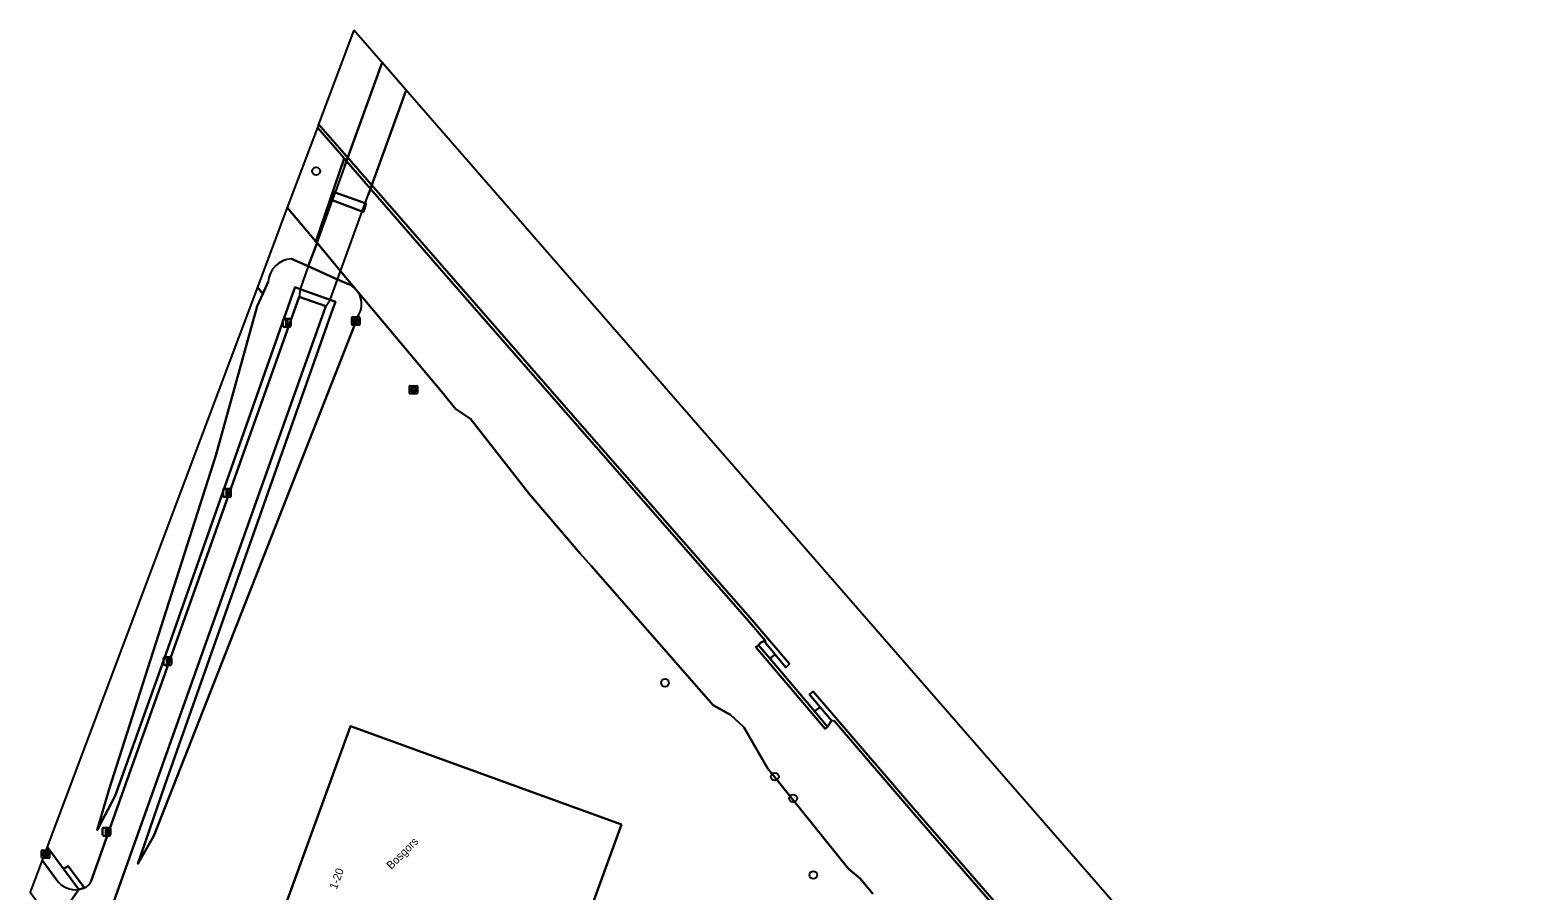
# Model space of a CAD drawing. Extents: x 156661 to 157576, y 383570 to 384425.
# Drawn here: x 156828.2 to 157016.4, y 384317.7 to 384425.3 of the extents above; entities that cross this region are included whole.
import ezdxf

# ---------------------------------------------------------------- set-up
doc = ezdxf.new("R2010")
doc.units = 0
for name, color, linetype in [('IMGEO_Boom', 7, 'Continuous'), ('IMGEO_Dek', 7, 'Continuous'), ('IMGEO_Fietspad_gesloten', 7, 'Continuous'), ('IMGEO_Fietspad_open', 7, 'Continuous'), ('IMGEO_Gemengd_bos', 7, 'Continuous'), ('IMGEO_Groenvoorziening', 7, 'Continuous'), ('IMGEO_Haag', 7, 'Continuous'), ('IMGEO_Hek', 7, 'Continuous'), ('IMGEO_Houtwal', 7, 'Continuous'), ('IMGEO_Kademuur', 7, 'Continuous'), ('IMGEO_Kast', 7, 'Continuous'), ('IMGEO_Lichtmast', 7, 'Continuous'), ('IMGEO_Loofbos', 7, 'Continuous'), ('IMGEO_Oever', 7, 'Continuous'), ('IMGEO_Openbare_ruimte_label', 7, 'Continuous'), ('IMGEO_Pand', 7, 'Continuous'), ('IMGEO_Pand_nummerreeks', 7, 'Continuous'), ('IMGEO_Pijler', 7, 'Continuous'), ('IMGEO_Rioolput', 7, 'Continuous'), ('IMGEO_Voetpad_open', 7, 'Continuous'), ('IMGEO_Waterloop', 7, 'Continuous')]:
    doc.layers.add(name, color=color, linetype=linetype)

msp = doc.modelspace()

# ---------------------------------------------------------------- linework, layer by layer
at = {"layer": 'IMGEO_Boom'}
for centre in [(156863.91, 384407.68), (156907.51, 384343.72), (156921.23, 384331.99), (156923.52, 384329.29), (156926.04, 384319.71)]:
    msp.add_circle(centre, 0.489, dxfattribs=at)
at = {"layer": 'IMGEO_Dek'}
msp.add_lwpolyline([(156875.15, 384417.82), (156872.14, 384421.27), (156867.44, 384408.27), (156866.27, 384405.03), (156865.9, 384404.04), (156863.99, 384398.74), (156862.92, 384395.79), (156861.89, 384392.95), (156861.79, 384391.99), (156865.12, 384390.79), (156865.67, 384391.6), (156866.59, 384394.15), (156866.96, 384395.19), (156869.67, 384402.65), (156870.04, 384403.68), (156870.44, 384404.8)], close=True, dxfattribs=at)
at = {"layer": 'IMGEO_Fietspad_gesloten'}
msp.add_lwpolyline([(156875.15, 384417.82), (156872.14, 384421.27), (156867.44, 384408.27), (156866.27, 384405.03), (156865.9, 384404.04), (156863.99, 384398.74), (156862.92, 384395.79), (156861.89, 384392.95), (156861.79, 384391.99), (156865.12, 384390.79), (156865.67, 384391.6), (156866.59, 384394.15), (156866.96, 384395.19), (156869.67, 384402.65), (156870.04, 384403.68), (156870.44, 384404.8)], close=True, dxfattribs=at)
for points in [[(156829.64, 384321.55), (156828.15, 384317.58), (156831.14, 384313.53), (156834.24, 384317.91)], [(156831.5, 384319.07), (156829.64, 384321.55)]]:
    msp.add_lwpolyline(points, dxfattribs=at)
msp.add_arc((156833.76, 384320.58), 2.71, 213.7247, 280.328, dxfattribs=at)
at = {"layer": 'IMGEO_Fietspad_open'}
for points in [[(156833.16, 384301.08), (156837.53, 384313.35), (156865.12, 384390.79), (156861.79, 384391.99), (156835.74, 384318.86)], [(156834.95, 384318.09), (156834.24, 384317.91), (156831.14, 384313.53)]]:
    msp.add_lwpolyline(points, dxfattribs=at)
msp.add_arc((156834.41, 384319.43), 1.44, 291.7855, 336.9714, dxfattribs=at)
at = {"layer": 'IMGEO_Gemengd_bos'}
for points in [[(156860.3, 384403.15), (156856.56, 384393.19), (156857.24, 384392.35), (156857.91, 384393.84)], [(156860.82, 384396.74), (156862.92, 384395.79), (156864.01, 384398.72), (156863.99, 384398.74), (156863.88, 384398.87), (156860.3, 384403.15)]]:
    msp.add_lwpolyline(points, dxfattribs=at)
msp.add_arc((156861.02, 384393.62), 3.12, 93.7377, 175.9662, dxfattribs=at)
at = {"layer": 'IMGEO_Groenvoorziening'}
for points in [[(156933.49, 384317.37), (156931.89, 384319.27), (156930.43, 384320.47), (156920.32, 384333.08), (156917.35, 384338.18), (156915.68, 384339.71), (156913.54, 384340.93), (156898.26, 384358.33), (156896.92, 384359.9), (156890.54, 384367.33), (156883.2, 384376.71), (156881.32, 384377.98), (156879.76, 384379.88), (156866.96, 384395.19), (156864.01, 384398.72), (156862.92, 384395.79), (156862.92, 384395.79), (156866.59, 384394.15), (156867.93, 384393.54)], [(156867.93, 384393.54), (156866.59, 384394.15), (156862.92, 384395.79), (156862.92, 384395.79), (156860.82, 384396.74)], [(156857.91, 384393.84), (156857.24, 384392.35), (156856.55, 384390.8), (156851.36, 384372.13), (156837.99, 384330.3), (156836.54, 384325.29), (156838.78, 384329.6), (156844.84, 384346.47), (156860.94, 384392.3), (156861.26, 384393.17), (156861.89, 384392.95), (156865.67, 384391.6), (156866.32, 384391.36), (156866, 384390.47), (156844.98, 384330.95), (156841.61, 384321.1), (156843.61, 384324.6), (156869.19, 384389.66)], [(156856.56, 384393.19), (156830.27, 384323.22), (156832.33, 384320.46), (156832.89, 384320.83), (156834.95, 384318.09)], [(156835.74, 384318.86), (156861.79, 384391.99), (156865.12, 384390.79), (156837.53, 384313.35)], [(156869.19, 384389.66), (156843.61, 384324.6), (156841.61, 384321.1), (156844.98, 384330.95), (156866, 384390.47), (156866.32, 384391.36), (156865.67, 384391.6), (156861.89, 384392.95), (156861.26, 384393.17), (156860.94, 384392.3), (156844.84, 384346.47), (156838.78, 384329.6), (156836.54, 384325.29), (156837.99, 384330.3), (156851.36, 384372.13), (156856.55, 384390.8), (156857.24, 384392.35), (156856.56, 384393.19)]]:
    msp.add_lwpolyline(points, dxfattribs=at)
for points in [[(156902.06, 384326.02), (156889.74, 384292.16), (156855.89, 384304.48), (156868.2, 384338.32)], [(156832.89, 384320.83), (156832.33, 384320.46), (156834.24, 384317.91), (156834.95, 384318.09)]]:
    msp.add_lwpolyline(points, close=True, dxfattribs=at)
for centre, radius, start, end in [((156861.02, 384393.62), 3.12, 93.7377, 175.9662), ((156866.88, 384391.06), 2.7, 328.804, 67.0801), ((156866.88, 384391.06), 2.7, 328.804, 67.0801), ((156834.41, 384319.43), 1.44, 291.7855, 336.9714)]:
    msp.add_arc(centre, radius, start, end, dxfattribs=at)
at = {"layer": 'IMGEO_Haag'}
msp.add_lwpolyline([(156832.89, 384320.83), (156832.33, 384320.46), (156834.24, 384317.91), (156834.95, 384318.09)], close=True, dxfattribs=at)
at = {"layer": 'IMGEO_Hek'}
for points in [[(156867.44, 384408.27), (156872.14, 384421.27)], [(156875.15, 384417.82), (156870.44, 384404.8)], [(156867.44, 384408.27), (156866.27, 384405.03)], [(156866.27, 384405.03), (156865.9, 384404.04)], [(156865.9, 384404.04), (156863.99, 384398.74)], [(156869.67, 384402.65), (156870.04, 384403.68)], [(156870.04, 384403.68), (156870.44, 384404.8)], [(156866.96, 384395.19), (156869.67, 384402.65)], [(156863.99, 384398.74), (156862.92, 384395.79)], [(156862.92, 384395.79), (156861.89, 384392.95)], [(156865.67, 384391.6), (156866.59, 384394.15)], [(156866.59, 384394.15), (156866.96, 384395.19)], [(156861.89, 384392.95), (156861.79, 384391.99)], [(156865.12, 384390.79), (156865.67, 384391.6)]]:
    msp.add_lwpolyline(points, dxfattribs=at)
at = {"layer": 'IMGEO_Houtwal'}
msp.add_lwpolyline([(156962.3, 384300.1), (156938.72, 384327.24), (156928.69, 384338.92), (156928.32, 384339.01), (156928.08, 384338.61), (156927.83, 384338.23), (156927.53, 384337.97), (156918.87, 384348.18), (156919.18, 384348.44), (156919.46, 384348.73), (156920.02, 384349.03), (156917.83, 384351.59), (156898.91, 384373.2), (156880.46, 384394.28), (156867.42, 384409.25), (156863.88, 384398.87), (156863.99, 384398.74), (156864.01, 384398.72), (156866.96, 384395.19), (156879.76, 384379.88), (156881.32, 384377.98), (156883.2, 384376.71), (156890.54, 384367.33), (156896.92, 384359.9), (156898.26, 384358.33), (156913.54, 384340.93), (156915.68, 384339.71), (156917.35, 384338.18), (156920.32, 384333.08), (156930.43, 384320.47), (156931.89, 384319.27), (156933.49, 384317.37)], dxfattribs=at)
msp.add_lwpolyline([(156865.9, 384404.04), (156865.78, 384404.08), (156866.13, 384405.08), (156866.27, 384405.03), (156870.04, 384403.68), (156870.17, 384403.63), (156869.83, 384402.6), (156869.67, 384402.65)], close=True, dxfattribs=at)
at = {"layer": 'IMGEO_Kademuur'}
for points in [[(156864.05, 384413.13), (156867.1, 384409.62), (156867.42, 384409.25), (156880.46, 384394.28), (156898.91, 384373.2), (156917.83, 384351.59), (156920.02, 384349.03), (156920.06, 384348.72), (156921.28, 384347.25), (156922.61, 384345.65), (156923.08, 384346.1), (156918.13, 384351.86), (156899.21, 384373.46), (156880.76, 384394.54), (156867.4, 384409.88), (156864.21, 384413.56)], [(156920.67, 384346.67), (156919.18, 384348.44), (156918.87, 384348.18), (156927.53, 384337.97), (156927.83, 384338.23), (156926.19, 384340.17)], [(157006.31, 384248.53), (156993.04, 384263.6), (156992.33, 384266.34), (156983.82, 384276.03), (156962.6, 384300.36), (156939.02, 384327.5), (156926.02, 384342.63), (156925.56, 384342.27), (156926.89, 384340.7), (156928.32, 384339.01), (156928.69, 384338.92), (156938.72, 384327.24), (156962.3, 384300.1), (156983.52, 384275.77), (156991.97, 384266.15), (156992.67, 384263.41), (157006.01, 384248.27), (157023.54, 384228.05), (157023.76, 384227.8), (157025.56, 384225.77), (157026.74, 384224.43), (157027.04, 384224.69), (157023.85, 384228.32)]]:
    msp.add_lwpolyline(points, close=True, dxfattribs=at)
at = {"layer": 'IMGEO_Kast'}
for p, q in [((156868.35, 384388.53), (156868.35, 384389.37)), ((156868.35, 384389.37), (156868.35, 384388.53)), ((156868.43, 384389.45), (156869.27, 384389.45)), ((156869.27, 384389.45), (156868.43, 384389.45)), ((156869.28, 384388.46), (156868.44, 384388.46)), ((156868.44, 384388.46), (156869.28, 384388.46)), ((156869.35, 384389.38), (156869.35, 384388.54)), ((156869.35, 384388.54), (156869.35, 384389.38))]:
    msp.add_line(p, q, dxfattribs=at)
for points in [[(156868.55, 384389.25), (156869.15, 384389.25), (156869.15, 384389.16), (156868.55, 384389.16), (156868.55, 384389.25)], [(156868.55, 384389.07), (156869.15, 384389.07), (156869.15, 384388.58), (156868.55, 384388.58), (156868.55, 384389.07)]]:
    msp.add_lwpolyline(points, dxfattribs=at)
msp.add_circle((156868.63, 384388.92), 0.0377, dxfattribs=at)
for centre, start, end in [((156868.43, 384389.38), 92.4484, 184.2845), ((156868.43, 384389.38), 92.4484, 184.2845), ((156868.43, 384388.53), 182.4484, 274.2845), ((156868.43, 384388.53), 182.4484, 274.2845), ((156869.27, 384389.38), 2.4484, 94.2845), ((156869.27, 384389.38), 2.4484, 94.2845), ((156869.27, 384388.53), 272.4484, 4.2845), ((156869.27, 384388.53), 272.4484, 4.2845)]:
    msp.add_arc(centre, 0.0779, start, end, dxfattribs=at)
at = {"layer": 'IMGEO_Lichtmast'}
for p, q in [((156859.74, 384388.32), (156859.74, 384389.12)), ((156859.74, 384389.12), (156859.74, 384388.32)), ((156859.84, 384389.22), (156860.63, 384389.22)), ((156860.63, 384389.22), (156859.84, 384389.22)), ((156860.63, 384388.22), (156859.84, 384388.22)), ((156859.84, 384388.22), (156860.63, 384388.22)), ((156860.73, 384389.12), (156860.73, 384388.32)), ((156860.73, 384388.32), (156860.73, 384389.12)), ((156852.26, 384367.06), (156852.26, 384367.86)), ((156852.26, 384367.86), (156852.26, 384367.06)), ((156852.36, 384367.96), (156853.15, 384367.96)), ((156853.15, 384367.96), (156852.36, 384367.96)), ((156853.25, 384367.86), (156853.25, 384367.06)), ((156853.25, 384367.06), (156853.25, 384367.86)), ((156853.15, 384366.96), (156852.36, 384366.96)), ((156852.36, 384366.96), (156853.15, 384366.96)), ((156844.83, 384346.03), (156844.83, 384346.83)), ((156844.83, 384346.83), (156844.83, 384346.03)), ((156844.93, 384346.93), (156845.72, 384346.93)), ((156845.72, 384346.93), (156844.93, 384346.93)), ((156845.82, 384346.83), (156845.82, 384346.03)), ((156845.82, 384346.03), (156845.82, 384346.83)), ((156845.72, 384345.93), (156844.93, 384345.93)), ((156844.93, 384345.93), (156845.72, 384345.93)), ((156837.2, 384324.72), (156837.2, 384325.52)), ((156837.2, 384325.52), (156837.2, 384324.72)), ((156837.3, 384325.62), (156838.09, 384325.62)), ((156838.09, 384325.62), (156837.3, 384325.62)), ((156838.09, 384324.62), (156837.3, 384324.62)), ((156837.3, 384324.62), (156838.09, 384324.62)), ((156838.19, 384325.52), (156838.19, 384324.72)), ((156838.19, 384324.72), (156838.19, 384325.52))]:
    msp.add_line(p, q, dxfattribs=at)
for points in [[(156860.16, 384389.09), (156860.31, 384389.09), (156860.31, 384388.34), (156860.16, 384388.34), (156860.16, 384389.09)], [(156852.68, 384367.84), (156852.83, 384367.84), (156852.83, 384367.09), (156852.68, 384367.09), (156852.68, 384367.84)], [(156845.25, 384346.8), (156845.4, 384346.8), (156845.4, 384346.05), (156845.25, 384346.05), (156845.25, 384346.8)], [(156837.62, 384325.49), (156837.77, 384325.49), (156837.77, 384324.74), (156837.62, 384324.74), (156837.62, 384325.49)]]:
    msp.add_lwpolyline(points, dxfattribs=at)
for centre, start, end in [((156859.84, 384389.12), 90, 180), ((156859.84, 384389.12), 90, 180), ((156859.84, 384388.32), 180, 270), ((156859.84, 384388.32), 180, 270), ((156860.63, 384389.12), 0, 90), ((156860.63, 384389.12), 360, 90), ((156860.63, 384388.32), 270, 0), ((156860.63, 384388.32), 270, 0), ((156852.36, 384367.86), 90, 180), ((156852.36, 384367.86), 90, 180), ((156853.15, 384367.86), 0, 90), ((156853.15, 384367.86), 360, 90), ((156852.36, 384367.06), 180, 270), ((156852.36, 384367.06), 180, 270), ((156853.15, 384367.06), 270, 0), ((156853.15, 384367.06), 270, 0), ((156844.93, 384346.83), 90, 180), ((156844.93, 384346.83), 90, 180), ((156845.72, 384346.83), 0, 90), ((156845.72, 384346.83), 360, 90), ((156844.93, 384346.03), 180, 270), ((156844.93, 384346.03), 180, 270), ((156845.72, 384346.03), 270, 0), ((156845.72, 384346.03), 270, 0), ((156837.3, 384325.52), 90, 180), ((156837.3, 384325.52), 90, 180), ((156837.3, 384324.72), 180, 270), ((156837.3, 384324.72), 180, 270), ((156838.09, 384325.52), 0, 90), ((156838.09, 384325.52), 360, 90), ((156838.09, 384324.72), 270, 0), ((156838.09, 384324.72), 270, 0)]:
    msp.add_arc(centre, 0.1, start, end, dxfattribs=at)
at = {"layer": 'IMGEO_Loofbos'}
msp.add_lwpolyline([(156864.05, 384413.13), (156860.3, 384403.15), (156863.88, 384398.87), (156867.42, 384409.25), (156867.1, 384409.62)], close=True, dxfattribs=at)
at = {"layer": 'IMGEO_Oever'}
for points in [[(156920.06, 384348.72), (156920.02, 384349.03), (156919.46, 384348.73), (156919.18, 384348.44), (156920.67, 384346.67), (156920.82, 384346.94), (156921.28, 384347.25)], [(156926.89, 384340.7), (156926.43, 384340.35), (156926.19, 384340.17), (156927.83, 384338.23), (156928.08, 384338.61), (156928.32, 384339.01)]]:
    msp.add_lwpolyline(points, close=True, dxfattribs=at)
at = {"layer": 'IMGEO_Pand'}
msp.add_lwpolyline([(156902.06, 384326.02), (156868.2, 384338.32), (156855.89, 384304.48), (156889.74, 384292.16)], close=True, dxfattribs=at)
at = {"layer": 'IMGEO_Pijler'}
msp.add_lwpolyline([(156866.27, 384405.03), (156866.13, 384405.08), (156865.78, 384404.08), (156865.9, 384404.04), (156869.67, 384402.65), (156869.83, 384402.6), (156870.17, 384403.63), (156870.04, 384403.68)], close=True, dxfattribs=at)
at = {"layer": 'IMGEO_Rioolput'}
for p, q in [((156875.56, 384379.93), (156875.56, 384380.78)), ((156875.63, 384380.85), (156876.48, 384380.85)), ((156876.04, 384380.63), (156876.07, 384380.63)), ((156876.56, 384380.78), (156876.56, 384379.93)), ((156876.48, 384379.85), (156875.63, 384379.85)), ((156875.81, 384380.35), (156875.81, 384380.36)), ((156876.25, 384380.31), (156875.85, 384380.31)), ((156875.86, 384380.4), (156876.25, 384380.4)), ((156876.07, 384380.07), (156876.04, 384380.07)), ((156876.3, 384380.36), (156876.3, 384380.35)), ((156829.57, 384321.9), (156829.57, 384322.75)), ((156829.65, 384322.82), (156830.5, 384322.82)), ((156829.83, 384322.32), (156829.83, 384322.33)), ((156829.87, 384322.37), (156830.27, 384322.37)), ((156830.27, 384322.28), (156829.87, 384322.28)), ((156830.06, 384322.6), (156830.09, 384322.6)), ((156830.32, 384322.33), (156830.32, 384322.32)), ((156830.57, 384322.75), (156830.57, 384321.9)), ((156830.5, 384321.82), (156829.65, 384321.82)), ((156830.08, 384322.04), (156830.06, 384322.04))]:
    msp.add_line(p, q, dxfattribs=at)
for points in [[(156875.56, 384379.93), (156875.56, 384380.78)], [(156875.63, 384380.85), (156876.48, 384380.85)], [(156876.56, 384380.78), (156876.56, 384379.93)], [(156876.48, 384379.85), (156875.63, 384379.85)], [(156829.57, 384321.9), (156829.57, 384322.75)], [(156829.65, 384322.82), (156830.5, 384322.82)], [(156830.57, 384322.75), (156830.57, 384321.9)], [(156830.5, 384321.82), (156829.65, 384321.82)]]:
    msp.add_lwpolyline(points, dxfattribs=at)
for centre, radius, start, end in [((156875.63, 384380.78), 0.0765, 91.552, 178.448), ((156875.63, 384380.78), 0.0765, 91.552, 178.448), ((156876.48, 384380.78), 0.0765, 1.552, 88.448), ((156876.48, 384380.78), 0.0765, 1.552, 88.448), ((156875.63, 384379.93), 0.0765, 181.552, 268.448), ((156875.63, 384379.93), 0.0765, 181.552, 268.448), ((156875.85, 384380.36), 0.0403, 85.8775, 175.7526), ((156875.85, 384380.35), 0.0366, 178.938, 274.7102), ((156876.26, 384380.36), 0.0386, 1.7309, 96.639), ((156876.26, 384380.35), 0.043, 264.8664, 352.4533), ((156876.48, 384379.93), 0.0765, 271.552, 358.448), ((156876.48, 384379.93), 0.0765, 271.552, 358.448), ((156829.65, 384322.75), 0.0765, 91.552, 178.448), ((156829.65, 384322.75), 0.0765, 91.552, 178.448), ((156829.87, 384322.33), 0.0403, 85.8775, 175.7526), ((156829.87, 384322.32), 0.0366, 178.938, 274.7102), ((156830.28, 384322.33), 0.0386, 1.7309, 96.639), ((156830.27, 384322.32), 0.043, 264.8664, 352.4533), ((156830.5, 384322.75), 0.0765, 1.552, 88.448), ((156830.5, 384322.75), 0.0765, 1.552, 88.448), ((156829.65, 384321.9), 0.0765, 181.552, 268.448), ((156829.65, 384321.9), 0.0765, 181.552, 268.448), ((156830.5, 384321.9), 0.0765, 271.552, 358.448), ((156830.5, 384321.9), 0.0765, 271.552, 358.448)]:
    msp.add_arc(centre, radius, start, end, dxfattribs=at)
for centre, major_axis, ratio, start_param, end_param in [((156876.04, 384380.35), (-0.387, 0.002), 0.722429, 4.712389, 7.853982), ((156876.07, 384380.35), (-0.39, 0.002), 0.717154, 1.570796, 4.712389), ((156830.06, 384322.32), (-0.387, 0.002), 0.722429, 4.712389, 7.853982), ((156830.08, 384322.32), (-0.39, 0.002), 0.717154, 1.570796, 4.712389)]:
    msp.add_ellipse(centre, major_axis=major_axis, ratio=ratio, start_param=start_param, end_param=end_param, dxfattribs=at)
at = {"layer": 'IMGEO_Voetpad_open'}
for points in [[(156830.27, 384323.22), (156829.64, 384321.55), (156831.5, 384319.07)], [(156834.24, 384317.91), (156832.33, 384320.46), (156830.27, 384323.22)]]:
    msp.add_lwpolyline(points, dxfattribs=at)
msp.add_arc((156833.76, 384320.58), 2.71, 213.7247, 280.328, dxfattribs=at)
at = {"layer": 'IMGEO_Waterloop'}
for points in [[(156868.63, 384425.31), (156864.21, 384413.56), (156867.4, 384409.88), (156880.76, 384394.54), (156899.21, 384373.46), (156918.13, 384351.86), (156923.08, 384346.1), (156922.61, 384345.65), (156921.28, 384347.25), (156920.82, 384346.94), (156920.67, 384346.67), (156926.19, 384340.17), (156926.43, 384340.35), (156926.89, 384340.7), (156925.56, 384342.27), (156926.02, 384342.63), (156939.02, 384327.5), (156962.6, 384300.36), (156983.82, 384276.03), (156992.33, 384266.34), (156993.04, 384263.6), (157006.31, 384248.53), (157023.85, 384228.32)], [(157335.95, 383888.66), (157157.55, 384093.52), (156868.63, 384425.31)]]:
    msp.add_lwpolyline(points, dxfattribs=at)

# ---------------------------------------------------------------- texts
at = {"layer": 'IMGEO_Openbare_ruimte_label'}
msp.add_text('Bosgors', height=1, rotation=45, dxfattribs=at).set_placement((156873.3, 384320.34))
at = {"layer": 'IMGEO_Pand_nummerreeks'}
msp.add_text('1-20', height=1, rotation=70.0154, dxfattribs=at).set_placement((156866.47, 384317.82))

doc.saveas('drawing.dxf')
